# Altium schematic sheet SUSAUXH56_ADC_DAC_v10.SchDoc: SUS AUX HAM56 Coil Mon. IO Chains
size B; Engineer: L. Sanchez; Organization: LIGO Laboratory; Address1: California Institute of Technology; Address2: Massachusetts Institute of Technology; DocumentNumber: D1002740; Revision: v10; SheetNumber: 6; SheetTotal: 8
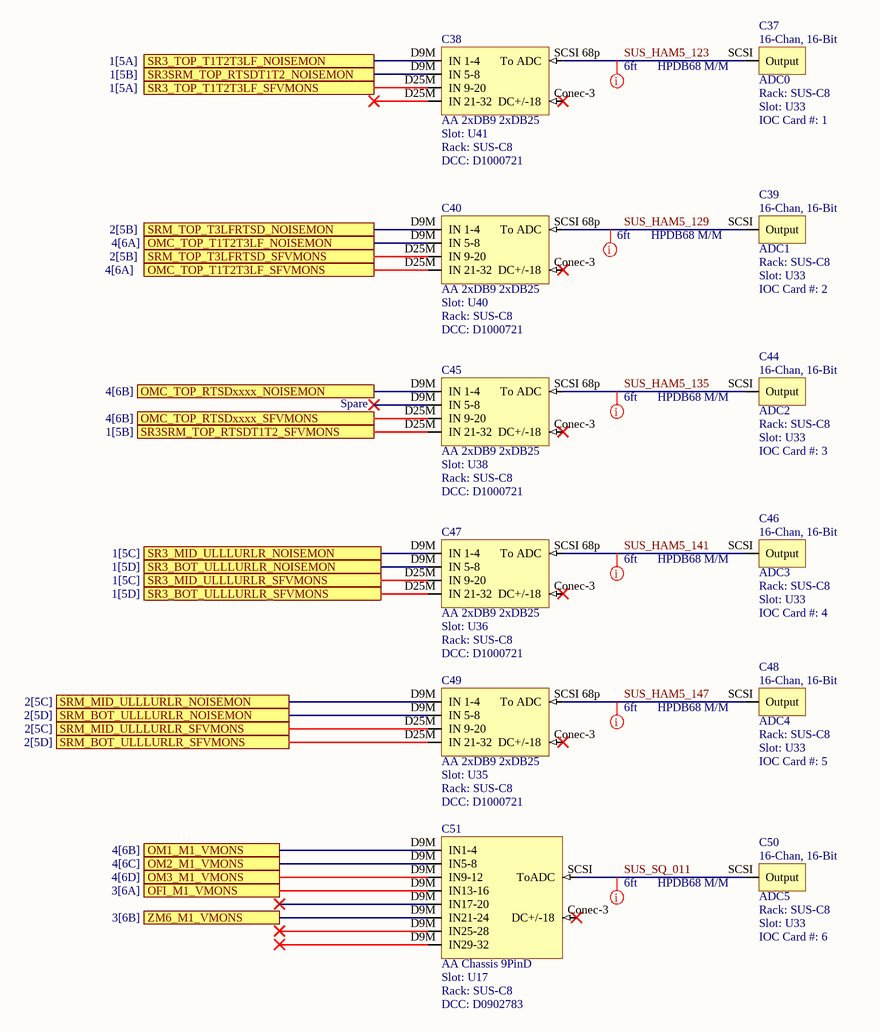
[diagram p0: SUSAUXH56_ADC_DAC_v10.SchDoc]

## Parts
C37  ADC0  Rack: SUS-C8  Slot: U33  IOC Card #: 1
C38  AA 2xDB9 2xDB25  Slot: U41  Rack: SUS-C8  DCC: D1000721
C39  ADC1  Rack: SUS-C8  Slot: U33  IOC Card #: 2
C40  AA 2xDB9 2xDB25  Slot: U40  Rack: SUS-C8  DCC: D1000721
C44  ADC2  Rack: SUS-C8  Slot: U33  IOC Card #: 3
C45  AA 2xDB9 2xDB25  Slot: U38  Rack: SUS-C8  DCC: D1000721
C46  ADC3  Rack: SUS-C8  Slot: U33  IOC Card #: 4
C47  AA 2xDB9 2xDB25  Slot: U36  Rack: SUS-C8  DCC: D1000721
C48  ADC4  Rack: SUS-C8  Slot: U33  IOC Card #: 5
C49  AA 2xDB9 2xDB25  Slot: U35  Rack: SUS-C8  DCC: D1000721
C50  ADC5  Rack: SUS-C8  Slot: U33  IOC Card #: 6
C51  AA Chassis 9PinD  Slot: U17  Rack: SUS-C8  DCC: D0902783

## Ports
OFI_M1_VMONS (see 3[6A]), OM1_M1_VMONS (see 4[6B]), OM2_M1_VMONS (see 4[6C]), OM3_M1_VMONS (see 4[6D]), OMC_TOP_RTSDxxxx_NOISEMON (see 4[6B]), OMC_TOP_RTSDxxxx_SFVMONS (see 4[6B]), OMC_TOP_T1T2T3LF_NOISEMON (see 4[6A]), OMC_TOP_T1T2T3LF_SFVMONS (see 4[6A]), SR3_BOT_ULLLURLR_NOISEMON (see 1[5D]), SR3_BOT_ULLLURLR_SFVMONS (see 1[5D]), SR3_MID_ULLLURLR_NOISEMON (see 1[5C]), SR3_MID_ULLLURLR_SFVMONS (see 1[5C]), SR3_TOP_T1T2T3LF_NOISEMON (see 1[5A]), SR3_TOP_T1T2T3LF_SFVMONS (see 1[5A]), SR3SRM_TOP_RTSDT1T2_NOISEMON (see 1[5B]), SR3SRM_TOP_RTSDT1T2_SFVMONS (see 1[5B]), SRM_BOT_ULLLURLR_NOISEMON (see 2[5D]), SRM_BOT_ULLLURLR_SFVMONS (see 2[5D]), SRM_MID_ULLLURLR_NOISEMON (see 2[5C]), SRM_MID_ULLLURLR_SFVMONS (see 2[5C]), SRM_TOP_T3LFRTSD_NOISEMON (see 2[5B]), SRM_TOP_T3LFRTSD_SFVMONS (see 2[5B]), ZM6_M1_VMONS (see 3[6B])

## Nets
OFI_M1_VMONS: C51.D9M(IN13-16) ; port OFI_M1_VMONS
OM1_M1_VMONS: C51.D9M(IN1-4) ; port OM1_M1_VMONS
OM2_M1_VMONS: C51.D9M(IN5-8) ; port OM2_M1_VMONS
OM3_M1_VMONS: C51.D9M(IN9-12) ; port OM3_M1_VMONS
OMC_TOP_RTSDxxxx_NOISEMON: C45.D9M(IN_1-4) ; port OMC_TOP_RTSDxxxx_NOISEMON
OMC_TOP_RTSDxxxx_SFVMONS: C45.D25M(IN_9-20) ; port OMC_TOP_RTSDxxxx_SFVMONS
OMC_TOP_T1T2T3LF_NOISEMON: C40.D9M(IN_5-8) ; port OMC_TOP_T1T2T3LF_NOISEMON
OMC_TOP_T1T2T3LF_SFVMONS: C40.D25M(IN_21-32) ; port OMC_TOP_T1T2T3LF_SFVMONS
SR3_BOT_ULLLURLR_NOISEMON: C47.D9M(IN_5-8) ; port SR3_BOT_ULLLURLR_NOISEMON
SR3_BOT_ULLLURLR_SFVMONS: C47.D25M(IN_21-32) ; port SR3_BOT_ULLLURLR_SFVMONS
SR3_MID_ULLLURLR_NOISEMON: C47.D9M(IN_1-4) ; port SR3_MID_ULLLURLR_NOISEMON
SR3_MID_ULLLURLR_SFVMONS: C47.D25M(IN_9-20) ; port SR3_MID_ULLLURLR_SFVMONS
SR3_TOP_T1T2T3LF_NOISEMON: C38.D9M(IN_1-4) ; port SR3_TOP_T1T2T3LF_NOISEMON
SR3_TOP_T1T2T3LF_SFVMONS: C38.D25M(IN_9-20) ; port SR3_TOP_T1T2T3LF_SFVMONS
SR3SRM_TOP_RTSDT1T2_NOISEMON: C38.D9M(IN_5-8) ; port SR3SRM_TOP_RTSDT1T2_NOISEMON
SR3SRM_TOP_RTSDT1T2_SFVMONS: C45.D25M(IN_21-32) ; port SR3SRM_TOP_RTSDT1T2_SFVMONS
SRM_BOT_ULLLURLR_NOISEMON: C49.D9M(IN_5-8) ; port SRM_BOT_ULLLURLR_NOISEMON
SRM_BOT_ULLLURLR_SFVMONS: C49.D25M(IN_21-32) ; port SRM_BOT_ULLLURLR_SFVMONS
SRM_MID_ULLLURLR_NOISEMON: C49.D9M(IN_1-4) ; port SRM_MID_ULLLURLR_NOISEMON
SRM_MID_ULLLURLR_SFVMONS: C49.D25M(IN_9-20) ; port SRM_MID_ULLLURLR_SFVMONS
SRM_TOP_T3LFRTSD_NOISEMON: C40.D9M(IN_1-4) ; port SRM_TOP_T3LFRTSD_NOISEMON
SRM_TOP_T3LFRTSD_SFVMONS: C40.D25M(IN_9-20) ; port SRM_TOP_T3LFRTSD_SFVMONS
SUS_HAM5_123: C37.SCSI(Output) C38.SCSI_68p(To_ADC)
SUS_HAM5_129: C39.SCSI(Output) C40.SCSI_68p(To_ADC)
SUS_HAM5_135: C44.SCSI(Output) C45.SCSI_68p(To_ADC)
SUS_HAM5_141: C46.SCSI(Output) C47.SCSI_68p(To_ADC)
SUS_HAM5_147: C48.SCSI(Output) C49.SCSI_68p(To_ADC)
SUS_SQ_011: C50.SCSI(Output) C51.SCSI(ToADC)
ZM6_M1_VMONS: C51.D9M(IN21-24) ; port ZM6_M1_VMONS

Not connected (* = marked no-connect by the designer): C38 Conec-3(DC+/-18)*; C40 Conec-3(DC+/-18)*; C45 Conec-3(DC+/-18)*; C47 Conec-3(DC+/-18)*; C49 Conec-3(DC+/-18)*; C51 Conec-3(DC+/-18)*

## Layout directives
Length: 6ft; DCC: HPDB68 M/M: SUS_HAM5_123, SUS_HAM5_129, SUS_HAM5_135, SUS_HAM5_141, SUS_HAM5_147, SUS_SQ_011

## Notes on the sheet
- Spare

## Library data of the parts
C37 C39 C44 C46 C48 C50 = ADC-16: 16 Chan, 16 Bit ADC
C38 C40 C45 C47 C49 = AA 2xDB9M 2xDB25M: System: SUS; Serial: Sxxxxxxx
C51 = AA_9pinAll: ISC AA Chassis 9PinD; Serial: Sxxxxxxx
